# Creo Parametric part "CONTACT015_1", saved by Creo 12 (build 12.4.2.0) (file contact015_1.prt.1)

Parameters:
  PTC_WM_ITERATION = "0"
  PTC_WM_VERSION = "-.0"
  PTC_WM_LIFECYCLE_STATE = "In Work"
  PTC_WM_LIFECYCLE = "MO_CADDocument"
  PTC_WM_CREATED_BY = "Maximilian Roepper (Z0017RMS: MO)"
  PTC_WM_CREATED_ON = "18-Sep-26 11:36:42 AM"
  PTC_WM_MODIFIED_BY = "Maximilian Roepper (Z0017RMS: MO)"
  PTC_WM_MODIFIED_ON = "18-Sep-26 11:36:46 AM"
  PDMLINKNUMBER = "PDM000071454933"
  PTC_WM_NAME = "contact015_1.prt"
  PTC_WM_NUMBER = "PDM000071454933"

Other parameters: WEIGHT, WEIGHT_FACTOR, WEIGHT_ADD, _MASS_TEMP, _DIFF_TEMP, MC_ERRORS, SUPPLIER

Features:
  1. coordinate system
  2. datum plane "PRT_YZ"
  3. datum plane "PRT_XY"
  4. datum plane "PRT_XZ"
  5. coordinate system
  6. datum axis
  7. datum axis
  8. datum axis
  9. coordinate system
  10. imported feature

Other named items: PRT, SIEMENS_MO, DRW_VIEW_ORG, PRT_X, PRT_Y, PRT_Z, CS0, ROUGH_GROB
